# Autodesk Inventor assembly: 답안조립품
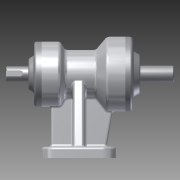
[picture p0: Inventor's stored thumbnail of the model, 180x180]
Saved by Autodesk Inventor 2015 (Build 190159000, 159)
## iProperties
Created: 2015-08
Part Number: 답안조립품
Document SubType Name: Assembly
Designer: PHO-1
Author: PHO-1
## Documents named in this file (10)
- C:\Users\PHO-1\Desktop\450805V1027\답안조립품.iam
- C:\Users\PHO-1\Desktop\450805V1027\본체.ipt
- C:\Users\PHO-1\Desktop\450805V1027\앞커버.ipt
- C:\Users\PHO-1\Desktop\450805V1027\베어링 6205.ipt
- C:\Users\PHO-1\Desktop\450805V1027\오일실 .ipt
- 오일실 .ipt
- C:\Users\PHO-1\Desktop\450805V1027\축.ipt
- C:\Users\PHO-1\Desktop\450805V1027\베어링 6203.ipt
- C:\Users\PHO-1\Desktop\450805V1027\뒤커버.ipt
- C:\Users\PHO-1\Desktop\450805V1027\M4x0.5.ipt
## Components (10 placed, 1 different names)
1. M4x0.5:1 — 각도:1
2. M4x0.5:2 — 각도:2
3. M4x0.5:3 — 각도:3
4. M4x0.5:4 — 각도:4
5. M4x0.5:5 — 각도:5
6. M4x0.5:6 — 각도:10
7. M4x0.5:7 — 각도:6
8. M4x0.5:8 — 각도:7
9. M4x0.5:9 — 각도:8
10. M4x0.5:10 — 각도:9
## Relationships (10: Angle 10)
- 각도:1 [Angle]: M4x0.5:1
- 각도:2 [Angle]: M4x0.5:2
- 각도:3 [Angle]: M4x0.5:3
- 각도:4 [Angle]: M4x0.5:4
- 각도:5 [Angle]: M4x0.5:5
- 각도:6 [Angle]: M4x0.5:7
- 각도:7 [Angle]: M4x0.5:8
- 각도:8 [Angle]: M4x0.5:9
- 각도:9 [Angle]: M4x0.5:10
- 각도:10 [Angle]: M4x0.5:6
